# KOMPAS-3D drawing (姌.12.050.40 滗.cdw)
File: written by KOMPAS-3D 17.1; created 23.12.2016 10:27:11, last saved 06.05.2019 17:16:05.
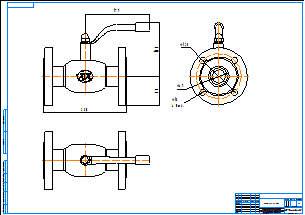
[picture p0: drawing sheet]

Sheet 1: A1, landscape

Title block, sheet 1: name: КШ.12.050.40 фф; material: Внимание! Данный продукт является объектом авторского права ООО «Торговый Дом АДЛ». / Запрещается изменение, копирование, распространение / (в том числе путем копирования на другие сайты и ресурсы в Интернете) / или любое иное использование информации и объектов без предварительного / согласия правообладателя (ООО «Торговый Дом АДЛ»).; sheets: 1; organisation: ООО "Торговый дом АДЛ"; sheet format: A1; stored path: C:\Users\tra\Desktop\2д чертежи\Шаровые краны БИВАЛ\КШ_Бивал_серия_11_12\KOMPAS_2D\КШ.12.050.40 фф.cdw

Views: Вид 1, Проекционный вид 2, Проекционный вид 3
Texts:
  Klimkovich
  ADL
Dimensions and other numbers on the sheet: 230; 179; 148; 80; 49; 18; 4 Отв.; 125; 1:1; 1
